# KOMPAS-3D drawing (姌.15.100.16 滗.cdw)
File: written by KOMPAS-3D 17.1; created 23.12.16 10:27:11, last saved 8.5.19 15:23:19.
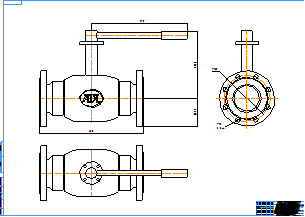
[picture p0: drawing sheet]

Sheet 1: A0, landscape

Title block, sheet 1: name: КШ.15.100.16 фф; material: Внимание! Данный продукт является объектом авторского права ООО «Торговый Дом АДЛ». / Запрещается изменение, копирование, распространение / (в том числе путем копирования на другие сайты и ресурсы в Интернете) / или любое иное использование информации и объектов без предварительного / согласия правообладателя (ООО «Торговый Дом АДЛ»).; sheets: 1; organisation: ООО "Торговый дом АДЛ"; sheet format: A0; stored path: C:\Users\tra\Desktop\2д чертежи\Шаровые краны БИВАЛ\КШ_Бивал_серия_14_15\KOMPAS_2D\КШ.15.100.16 фф.cdw

Views: Вид 1, Проекционный вид 2, Проекционный вид 3
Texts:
  Klimkovich
  ADL
Dimensions and other numbers on the sheet: 400; 370; 258,4; 107,5; 180; 18; 8 Отв.; 1:1; 1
